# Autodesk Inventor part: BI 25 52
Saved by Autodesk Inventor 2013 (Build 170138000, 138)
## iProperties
Created: 2012-12
Part Number: BI 25 52
Material: Générique
Document SubType Name: Modeling
Designer: jost thierry
Density: 1 g/cm^3
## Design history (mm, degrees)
node "BI 25 521"
node "BI 25 52"
node "Base1"
